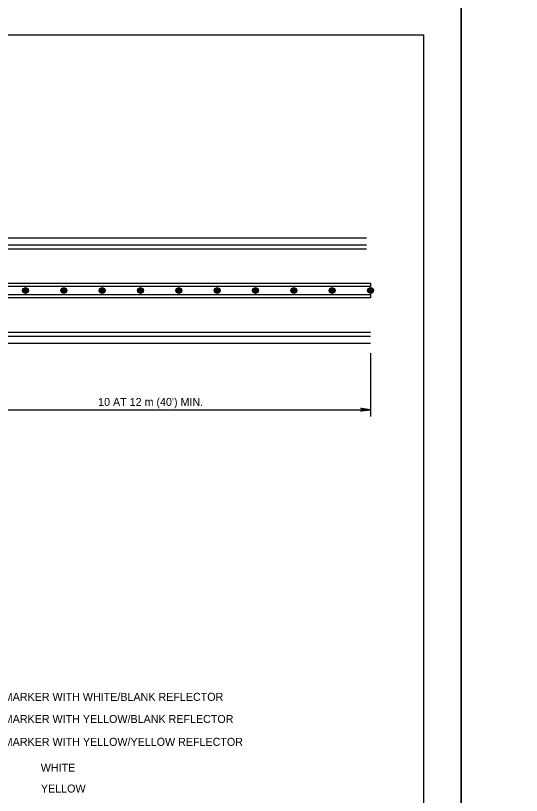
# Model space of a CAD drawing. Extents: x 639362 to 641108, y 298458 to 299646.
# Drawn here: x 640036.4 to 640225.9, y 298752.3 to 299044.4 of the extents above; entities that cross this region are included whole.
import ezdxf

# ---------------------------------------------------------------- set-up
doc = ezdxf.new("R2010")
doc.units = 0
for name, color, linetype in [('1', 7, 'Continuous'), ('2', 7, 'Continuous'), ('3', 7, 'Continuous'), ('PLT-BNDY', 7, 'Continuous')]:
    doc.layers.add(name, color=color, linetype=linetype)

# ---------------------------------------------------------------- blocks, each defined once
blk = doc.blocks.new('RARROW')
at = {"layer": '3'}
blk.add_lwpolyline([(-2.2695, 0.285), (-2.184875, 0.12075), (0, 0), (-2.2695, 0.285), (-2.38575, 0.384625), (0, 0), (-2.183125, -0.108), (-2.262875, -0.2705), (0, 0), (-2.38575, -0.379125), (-2.262875, -0.2705)], dxfattribs=at)

msp = doc.modelspace()

# ---------------------------------------------------------------- linework, layer by layer
at = {"layer": '1'}
for p in [(639403.27, 299037.19), (640189.27, 298473.19)]:
    msp.add_line(p, (640189.27, 299037.19), dxfattribs=at)
at = {"layer": '2'}
for p, q in [((640025.73, 298961.2), (640167.82, 298961.2)), ((640025.73, 298958.51), (640167.82, 298958.51)), ((640025.73, 298957.01), (640167.82, 298957.01)), ((640025.73, 298944.19), (640169.33, 298944.19)), ((640169.33, 298944.19), (640169.33, 298942.99)), ((640169.33, 298942.99), (640025.61, 298942.99)), ((640025.63, 298939.88), (640169.33, 298939.88)), ((640169.33, 298938.68), (640025.73, 298938.68)), ((640169.33, 298939.88), (640169.33, 298938.68)), ((640025.73, 298925.85), (640169.33, 298925.85)), ((640025.73, 298924.35), (640169.33, 298924.35)), ((640025.73, 298921.72), (640169.33, 298921.72)), ((640169.35, 298917.97), (640169.35, 298894.23)), ((640025.73, 298896.78), (640169.33, 298896.78))]:
    msp.add_line(p, q, dxfattribs=at)
for centre, radius in [((640040.09, 298941.43), 1.1), ((640040.09, 298941.43), 1.02), ((640040.09, 298941.43), 0.946), ((640040.09, 298941.43), 0.868), ((640040.09, 298941.43), 0.789), ((640040.09, 298941.43), 0.711), ((640040.09, 298941.43), 0.633), ((640040.09, 298941.43), 0.554), ((640040.09, 298941.43), 0.476), ((640040.09, 298941.43), 0.398), ((640040.09, 298941.43), 0.32), ((640040.09, 298941.43), 0.241), ((640040.09, 298941.43), 0.163), ((640040.09, 298941.43), 0.0846), ((640054.45, 298941.43), 1.1), ((640054.45, 298941.43), 1.02), ((640054.45, 298941.43), 0.946), ((640054.45, 298941.43), 0.868), ((640054.45, 298941.43), 0.789), ((640054.45, 298941.43), 0.711), ((640054.45, 298941.43), 0.633), ((640054.45, 298941.43), 0.554), ((640054.45, 298941.43), 0.476), ((640054.45, 298941.43), 0.398), ((640054.45, 298941.43), 0.32), ((640054.45, 298941.43), 0.241), ((640054.45, 298941.43), 0.163), ((640054.45, 298941.43), 0.0846), ((640068.81, 298941.43), 1.1), ((640068.81, 298941.43), 1.02), ((640068.81, 298941.43), 0.946), ((640068.81, 298941.43), 0.868), ((640068.81, 298941.43), 0.789), ((640068.81, 298941.43), 0.711), ((640068.81, 298941.43), 0.633), ((640068.81, 298941.43), 0.554), ((640068.81, 298941.43), 0.476), ((640068.81, 298941.43), 0.398), ((640068.81, 298941.43), 0.32), ((640068.81, 298941.43), 0.241), ((640068.81, 298941.43), 0.163), ((640068.81, 298941.43), 0.0846), ((640083.17, 298941.43), 1.1), ((640083.17, 298941.43), 1.02), ((640083.17, 298941.43), 0.946), ((640083.17, 298941.43), 0.868), ((640083.17, 298941.43), 0.789), ((640083.17, 298941.43), 0.711), ((640083.17, 298941.43), 0.633), ((640083.17, 298941.43), 0.554), ((640083.17, 298941.43), 0.476), ((640083.17, 298941.43), 0.398), ((640083.17, 298941.43), 0.32), ((640083.17, 298941.43), 0.241), ((640083.17, 298941.43), 0.163), ((640083.17, 298941.43), 0.0846), ((640097.53, 298941.43), 1.1), ((640097.53, 298941.43), 1.02), ((640097.53, 298941.43), 0.946), ((640097.53, 298941.43), 0.868), ((640097.53, 298941.43), 0.789), ((640097.53, 298941.43), 0.711), ((640097.53, 298941.43), 0.633), ((640097.53, 298941.43), 0.554), ((640097.53, 298941.43), 0.476), ((640097.53, 298941.43), 0.398), ((640097.53, 298941.43), 0.32), ((640097.53, 298941.43), 0.241), ((640097.53, 298941.43), 0.163), ((640097.53, 298941.43), 0.0846), ((640111.89, 298941.43), 1.1), ((640111.89, 298941.43), 1.02), ((640111.89, 298941.43), 0.946), ((640111.89, 298941.43), 0.868), ((640111.89, 298941.43), 0.789), ((640111.89, 298941.43), 0.711), ((640111.89, 298941.43), 0.633), ((640111.89, 298941.43), 0.554), ((640111.89, 298941.43), 0.476), ((640111.89, 298941.43), 0.398), ((640111.89, 298941.43), 0.32), ((640111.89, 298941.43), 0.241), ((640111.89, 298941.43), 0.163), ((640111.89, 298941.43), 0.0846), ((640126.25, 298941.43), 1.1), ((640126.25, 298941.43), 1.02), ((640126.25, 298941.43), 0.946), ((640126.25, 298941.43), 0.868), ((640126.25, 298941.43), 0.789), ((640126.25, 298941.43), 0.711), ((640126.25, 298941.43), 0.633), ((640126.25, 298941.43), 0.554), ((640126.25, 298941.43), 0.476), ((640126.25, 298941.43), 0.398), ((640126.25, 298941.43), 0.32), ((640126.25, 298941.43), 0.241), ((640126.25, 298941.43), 0.163), ((640126.25, 298941.43), 0.0846), ((640140.61, 298941.43), 1.1), ((640140.61, 298941.43), 1.02), ((640140.61, 298941.43), 0.946), ((640140.61, 298941.43), 0.868), ((640140.61, 298941.43), 0.789), ((640140.61, 298941.43), 0.711), ((640140.61, 298941.43), 0.633), ((640140.61, 298941.43), 0.554), ((640140.61, 298941.43), 0.476), ((640140.61, 298941.43), 0.398), ((640140.61, 298941.43), 0.32), ((640140.61, 298941.43), 0.241), ((640140.61, 298941.43), 0.163), ((640140.61, 298941.43), 0.0846), ((640154.97, 298941.43), 1.1), ((640154.97, 298941.43), 1.02), ((640154.97, 298941.43), 0.946), ((640154.97, 298941.43), 0.868), ((640154.97, 298941.43), 0.789), ((640154.97, 298941.43), 0.711), ((640154.97, 298941.43), 0.633), ((640154.97, 298941.43), 0.554), ((640154.97, 298941.43), 0.476), ((640154.97, 298941.43), 0.398), ((640154.97, 298941.43), 0.32), ((640154.97, 298941.43), 0.241), ((640154.97, 298941.43), 0.163), ((640154.97, 298941.43), 0.0846), ((640169.35, 298941.43), 1.1), ((640169.35, 298941.43), 1.02), ((640169.35, 298941.43), 0.946), ((640169.35, 298941.43), 0.868), ((640169.35, 298941.43), 0.789), ((640169.35, 298941.43), 0.711), ((640169.35, 298941.43), 0.633), ((640169.35, 298941.43), 0.554), ((640169.35, 298941.43), 0.476), ((640169.35, 298941.43), 0.398), ((640169.35, 298941.43), 0.32), ((640169.35, 298941.43), 0.241), ((640169.35, 298941.43), 0.163), ((640169.35, 298941.43), 0.0846)]:
    msp.add_circle(centre, radius, dxfattribs=at)
at = {"layer": 'PLT-BNDY'}
for points in [[(639362.31, 299051.63), (640203.31, 299051.63), (640203.31, 298457.63), (639362.31, 298457.63)], [(640203.31, 299051.63), (641044.31, 299051.63), (641044.31, 298457.63), (640203.31, 298457.63)]]:
    msp.add_lwpolyline(points, close=True, dxfattribs=at)

# ---------------------------------------------------------------- block references
at = {"layer": '2', "xscale": 1.5089217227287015, "yscale": 1.5711553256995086}
msp.add_blockref('RARROW', (640169.33, 298896.78), dxfattribs=at)

# ---------------------------------------------------------------- texts
at = {"layer": '2'}
for s, p in [("10 AT 12 m (40') MIN.", (640067.3, 298898.19)), ('TWO-WAY MARKER WITH WHITE/BLANK REFLECTOR', (640011, 298787.73)), ('TWO-WAY MARKER WITH YELLOW/YELLOW REFLECTOR', (640011, 298770.88)), ('WHITE', (640045.81, 298761.19)), ('YELLOW', (640045.88, 298753.38))]:
    msp.add_text(s, height=3, dxfattribs=at).set_placement(p)
msp.add_text('TWO-WAY MARKER WITH YELLOW/BLANK REFLECTOR', height=3, rotation=360, dxfattribs=at).set_placement((640011, 298779.44))

doc.saveas('drawing.dxf')
